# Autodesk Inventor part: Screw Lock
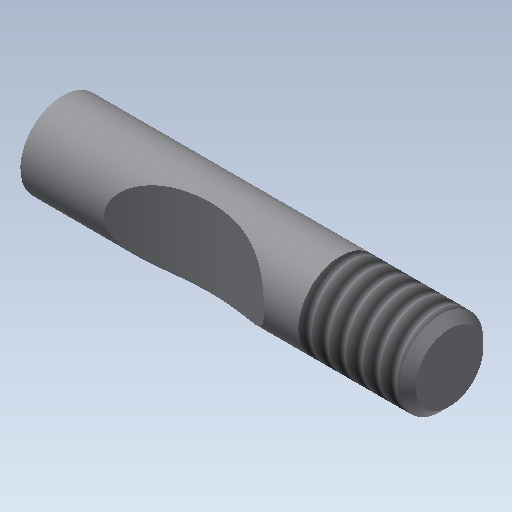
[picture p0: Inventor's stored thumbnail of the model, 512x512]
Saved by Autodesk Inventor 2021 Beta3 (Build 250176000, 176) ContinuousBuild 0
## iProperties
Created: 2012-08
Part Number: Screw Lock
Material: Generic
Document SubType Name: Modeling
Designer: John
Density: 1 g/cm^3
Appearance: Default
Author: John
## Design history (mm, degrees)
sketch "Sketch1"
  geometry: C1 r 1.968 at (0, 0); 1 further point
  constraints: 1 centre point, 1 coincident
  dimensions: "d0" = 3.937 diameter of C1
extrude "Extrusion1" new body sketch "Sketch1" distance "d1" = 18.034; taper "d2" = 0 deg
thread "Thread1" dims "d3" = 5.08, "d4" = 0
sketch "Sketch2"
  geometry: L1 (-18.034, 1.968)-(0, 1.968) reference; L2 (0, 1.968)-(0, -1.968) reference; L3 (0, -1.968)-(-18.034, -1.968) reference; L4 (-18.034, -1.968)-(-18.034, 1.968) reference; C1 r 6.223 at (-7.62, 6.947); 1 further point
  constraints: 1 centre point
  dimensions: "d6" = 7.62 distance from line of L2 C1.centre; "d7" = 4.9784 distance from line of L1 C1.centre; "d8" = 12.446 diameter of C1
extrude "Extrusion2" cut sketch "Sketch2" extent not by distance; stored distance "d9" = 18.034; taper "d10" = 0 deg
chamfer "Chamfer1" distance "d11" = 0.39687; stored, may be unused: second distance "d12" = 3.175, angle "d13" = 45 deg
body "Solid1"
node "Project Cut Edges1"
